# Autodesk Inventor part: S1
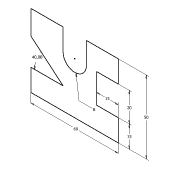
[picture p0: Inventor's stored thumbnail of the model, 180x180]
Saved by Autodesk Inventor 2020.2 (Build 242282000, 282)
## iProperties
Created: 2013-12
Part Number: S1
Material: Ogólny
Document SubType Name: Modeling
Designer: F.Stasiak
Density: 1 g/cm^3
Appearance: Domyślna
Manager: www.cadconsulting.pl
Company: Fabian Stasiak CAD Consulting
Author: F.Stasiak
Subject: Zbiór ćwiczeń. Autodesk Inventor 2020. Kurs podstawowy
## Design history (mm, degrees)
sketch "Szkic1"
  geometry: L1 (0, 0)-(60, 0); L2 (60, 0)-(60, 15); L3 (60, 15)-(45, 15); L4 (45, 15)-(45, 35); L5 (45, 35)-(60, 35); L6 (60, 35)-(60, 50); L7 (60, 50)-(38, 50); L8 (38, 50)-(38, 35); L9 (22, 35)-(22, 50); L10 (22, 50)-(0, 50); L11 (0, 50)-(0, 33.46); L12 (0, 33.46)-(22, 15); L13 (22, 15)-(0, 15); L14 (0, 15)-(0, 0); A1 r 8 centre (30, 35) between (22, 35) and (38, 35)
  constraints: 28 end point, 9 parallel, 6 collinear, 2 perpendicular, 2 point on circle, 2 point on line, 2 tangent, 1 centre point, 1 horizontal
  dimensions: "d0" = 60 distance of L1.start L1.end; "d1" = 15 distance of L1.end L2.end; "d2" = 15 distance of L2.end L3.end; "d3" = 20 distance of L3.end L4.end; "d4" = 50 distance between parallel lines of L1 L7; "d5" = 40 deg angle of L12 L13; "d6" = 8 radius of A1
